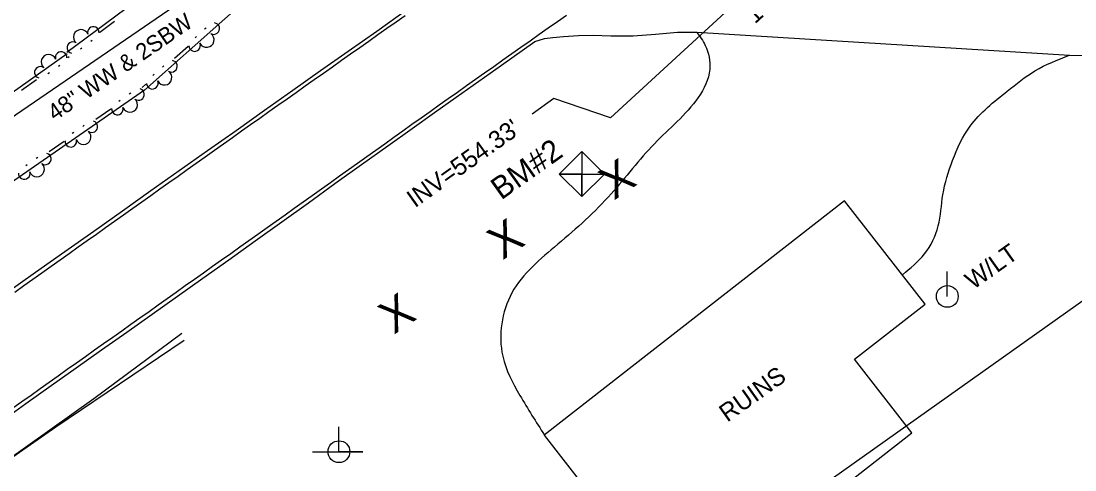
# Model space of a CAD drawing. Extents: x 1577032 to 1581865, y 611492 to 615011.
# Drawn here: x 1580168.3 to 1580404.9, y 613575.1 to 613675.8 of the extents above; entities that cross this region are included whole.
import ezdxf

# ---------------------------------------------------------------- set-up
doc = ezdxf.new("R2010")
doc.units = 0
for name, color, linetype in [('CTL Supplemental Vertical CELL', 7, 'Continuous'), ('CTL Supplemental Vertical Text', 7, 'Continuous'), ('Exist Guardrail', 7, 'Continuous'), ('Exist Other Culture Fence Line', 7, 'Continuous'), ('Exist Other Culture Fence Line Text', 7, 'Continuous'), ('Exist Property Owner Text', 7, 'Continuous'), ('Exist Right of Way Line', 7, 'Continuous'), ('Exist Roads EOP', 7, 'Continuous'), ('Exist Roads EOT', 7, 'Continuous'), ('Exist Structure Minor Pipes CMP 18 Inch Invert', 7, 'Continuous'), ('Exist Structure Minor Pipes CMP 18 Inch Leader', 7, 'Continuous'), ('Exist Structure Minor Pipes RCP 18 Inch', 7, 'Continuous'), ('Exist Structure Minor Pipes RCP 18 Inch Text', 7, 'Continuous'), ('Exist Utilities Power Joint Use Telephone CELL', 7, 'Continuous'), ('Exist Utilities Power Pole CELL', 7, 'Continuous'), ('Exist Utilities Power Pole Text', 7, 'Continuous'), ('Exist Vegetation Tree CELL', 7, 'Continuous'), ('Old_Level_11', 7, 'Continuous'), ('Old_Level_7', 7, 'Continuous'), ('Scratch_Level_4', 7, 'Continuous'), ('Scratch_Level_6', 7, 'Continuous')]:
    doc.layers.add(name, color=color, linetype=linetype)

msp = doc.modelspace()

# ---------------------------------------------------------------- linework, layer by layer
at = {"layer": 'CTL Supplemental Vertical CELL'}
msp.add_line((1580294.24, 613641.52), (1580294.24, 613641.52), dxfattribs=at)
for points in [[(1580289.16, 613641.49), (1580294.24, 613646.58), (1580299.32, 613641.49), (1580294.24, 613636.41), (1580289.16, 613641.49), (1580294.24, 613646.58), (1580299.32, 613641.49), (1580294.24, 613636.41), (1580289.16, 613641.49)], [(1580294.24, 613646.58), (1580294.24, 613636.41), (1580294.24, 613641.49), (1580289.16, 613641.49), (1580299.32, 613641.49)]]:
    msp.add_lwpolyline(points, dxfattribs=at)
at = {"layer": 'Exist Guardrail'}
msp.add_lwpolyline([(1580204.94, 613604.14), (1580176.13, 613584.66), (1580156.54, 613571.08), (1580137.28, 613557.36), (1580118.21, 613543.22), (1580106.98, 613535), (1580070.56, 613509.77), (1580039.34, 613487.9), (1579996.35, 613458.56), (1579960.14, 613434.1), (1579928.53, 613412.65), (1579891.13, 613387.42), (1579884.09, 613382.52), (1579876.58, 613377.52), (1579866.53, 613371.18), (1579856.35, 613364.93), (1579850.36, 613361.17), (1579845.45, 613357.94), (1579839.56, 613353.95), (1579830.4, 613347.61), (1579818.74, 613338.59)], dxfattribs=at)
at = {"layer": 'Exist Other Culture Fence Line'}
msp.add_line((1580098.64, 613607.82), (1580251.9, 613712.92), dxfattribs=at)
at = {"layer": 'Exist Right of Way Line'}
msp.add_line((1578304.92, 612120.6), (1580458.22, 613649.74), dxfattribs=at)
at = {"layer": 'Exist Roads EOP'}
for points in [[(1580254.88, 613678.24), (1580248.18, 613673.5), (1580241.77, 613668.98), (1580235.59, 613664.65), (1580229.34, 613660.25), (1580223, 613655.74), (1580216.6, 613651.2), (1580210.22, 613646.69), (1580203.84, 613642.2), (1580197.47, 613637.7), (1580191.09, 613633.18), (1580184.67, 613628.63), (1580178.17, 613624.03), (1580171.59, 613619.36), (1580164.85, 613614.58)], [(1580163.65, 613585.82), (1580169.43, 613589.97), (1580175.11, 613594.02), (1580180.75, 613598.02), (1580186.41, 613602.03), (1580192.1, 613606.04), (1580197.78, 613610.05), (1580203.45, 613614.05), (1580209.18, 613618.09), (1580215.01, 613622.24), (1580220.93, 613626.48), (1580226.88, 613630.75), (1580232.85, 613635.05), (1580238.81, 613639.34), (1580244.77, 613643.61), (1580250.66, 613647.81), (1580256.15, 613651.71), (1580261.18, 613655.29), (1580266.06, 613658.75), (1580271.12, 613662.33), (1580276.21, 613665.91), (1580283.68, 613671.25), (1580285.85, 613671.89), (1580287.7, 613672.14), (1580290.16, 613672.35), (1580293.46, 613672.55), (1580296.78, 613672.62), (1580300.73, 613672.52), (1580305.8, 613672.47), (1580310.79, 613672.84), (1580315.69, 613673.29), (1580320.02, 613673.33), (1580403.71, 613668.15)]]:
    msp.add_lwpolyline(points, dxfattribs=at)
msp.add_spline([(1580403.71, 613668.15), (1580454.87, 613667.32), (1580520.57, 613666.25), (1580608.23, 613664.83), (1580666.57, 613662.17), (1580712.03, 613659.84), (1580756.49, 613652.31), (1580801.49, 613639.76), (1580839.51, 613619.48), (1580875.28, 613593.59), (1580905.28, 613565.99), (1580935.48, 613537.65)], degree=3, dxfattribs=at)
at = {"layer": 'Exist Roads EOT'}
for points in [[(1580166.5, 613589), (1580168.54, 613590.45), (1580170.58, 613591.89), (1580172.61, 613593.34), (1580174.65, 613594.78), (1580176.69, 613596.23), (1580178.73, 613597.67), (1580180.77, 613599.12), (1580182.81, 613600.56), (1580184.84, 613602.01), (1580186.88, 613603.45), (1580188.92, 613604.9), (1580190.96, 613606.34), (1580193, 613607.78), (1580195.03, 613609.23), (1580197.07, 613610.67), (1580199.11, 613612.12), (1580201.15, 613613.56), (1580203.19, 613615.01), (1580205.22, 613616.45), (1580207.26, 613617.9), (1580209.3, 613619.34), (1580211.34, 613620.78), (1580213.38, 613622.23), (1580215.42, 613623.67), (1580217.45, 613625.12), (1580219.49, 613626.56), (1580221.53, 613628.01), (1580223.56, 613629.46), (1580225.6, 613630.91), (1580227.63, 613632.36), (1580229.67, 613633.81), (1580231.7, 613635.25), (1580233.73, 613636.7), (1580235.77, 613638.15), (1580237.8, 613639.6), (1580239.84, 613641.05), (1580241.87, 613642.5), (1580243.91, 613643.95), (1580245.94, 613645.4), (1580247.98, 613646.85), (1580250.01, 613648.3), (1580252.05, 613649.74), (1580254.08, 613651.19), (1580256.11, 613652.64), (1580258.15, 613654.09), (1580260.18, 613655.54), (1580262.22, 613656.99), (1580264.25, 613658.44), (1580266.29, 613659.88), (1580268.33, 613661.32), (1580270.37, 613662.76), (1580272.41, 613664.2), (1580274.46, 613665.64), (1580276.5, 613667.08), (1580278.54, 613668.52), (1580280.58, 613669.96), (1580282.62, 613671.4), (1580284.66, 613672.84), (1580286.7, 613674.28), (1580288.74, 613675.72), (1580290.78, 613677.16)], [(1580254.57, 613677.02), (1580252.53, 613675.58), (1580250.49, 613674.14), (1580248.45, 613672.7), (1580246.41, 613671.26), (1580244.37, 613669.82), (1580242.33, 613668.38), (1580240.29, 613666.93), (1580238.25, 613665.49), (1580236.21, 613664.05), (1580234.17, 613662.61), (1580232.13, 613661.17), (1580230.09, 613659.73), (1580228.05, 613658.29), (1580226.01, 613656.85), (1580223.97, 613655.41), (1580221.93, 613653.96), (1580219.89, 613652.52), (1580217.85, 613651.08), (1580215.81, 613649.64), (1580213.77, 613648.19), (1580211.74, 613646.75), (1580209.7, 613645.3), (1580207.66, 613643.86), (1580205.62, 613642.41), (1580203.59, 613640.96), (1580201.55, 613639.52), (1580199.51, 613638.07), (1580197.48, 613636.63), (1580195.44, 613635.18), (1580193.4, 613633.73), (1580191.36, 613632.29), (1580189.33, 613630.84), (1580187.29, 613629.4), (1580185.25, 613627.95), (1580183.22, 613626.5), (1580181.18, 613625.06), (1580179.14, 613623.61), (1580177.1, 613622.17), (1580175.07, 613620.72), (1580173.03, 613619.27), (1580171, 613617.83), (1580168.96, 613616.38), (1580166.92, 613614.93)]]:
    msp.add_lwpolyline(points, dxfattribs=at)
at = {"layer": 'Exist Structure Minor Pipes CMP 18 Inch Leader'}
msp.add_lwpolyline([(1580300.64, 613654.06), (1580287.96, 613658.4), (1580283.07, 613654.93)], dxfattribs=at)
at = {"layer": 'Exist Structure Minor Pipes RCP 18 Inch'}
msp.add_line((1580353.63, 613702.78), (1580300.64, 613654.06), dxfattribs=at)
msp.add_line((1580353.63, 613702.78), (1580300.64, 613654.06), dxfattribs=at)
at = {"layer": 'Exist Utilities Power Joint Use Telephone CELL'}
msp.add_line((1580239.7, 613579.18), (1580239.7, 613579.18), dxfattribs=at)
msp.add_lwpolyline([(1580233.77, 613579.18), (1580245.1, 613579.14), (1580239.7, 613579.16), (1580239.7, 613584.8)], dxfattribs=at)
msp.add_circle((1580239.71, 613579.18), 2.45, dxfattribs=at)
at = {"layer": 'Exist Utilities Power Pole CELL'}
for q in [(1580376.29, 613619.65), (1580376.29, 613614.03)]:
    msp.add_line((1580376.29, 613614.03), q, dxfattribs=at)
msp.add_circle((1580376.29, 613614.03), 2.45, dxfattribs=at)
at = {"layer": 'Old_Level_11'}
for points in [[(1580178.64, 613668.86), (1580237.64, 613712.65), (1580275.25, 613740.08), (1580305.41, 613763.08), (1580331.9, 613792.25), (1580348.57, 613817.56), (1580366.72, 613849.16), (1580382.81, 613883.89)], [(1580387.98, 613867.68), (1580362.26, 613826.06), (1580342.4, 613791.75), (1580326.53, 613768.18), (1580306.87, 613751.68), (1580263.54, 613718.08), (1580232.15, 613692.42), (1580196.05, 613660.28)], [(1580186.05, 613673.33), (1580189.34, 613675.78)], [(1580209.87, 613674.23), (1580209.56, 613673.96)], [(1580183.99, 613671.29), (1580184.32, 613671.54)], [(1580207.72, 613672.32), (1580207.41, 613672.05)], [(1580196.05, 613660.28), (1580125.81, 613611.65), (1580119.42, 613626.55), (1580178.67, 613668.56)], [(1580181.68, 613669.58), (1580182.01, 613669.83)], [(1580205.85, 613670.1), (1580202.78, 613667.38)], [(1580176.72, 613665.67), (1580177.06, 613665.91)], [(1580178.83, 613667.67), (1580179.14, 613667.89)], [(1580200.37, 613665.77), (1580200.06, 613665.5)], [(1580174.38, 613664.01), (1580174.72, 613664.25)], [(1580198.22, 613663.87), (1580197.92, 613663.6)], [(1580168.46, 613660.31), (1580171.8, 613662.68)], [(1580196.35, 613661.65), (1580195.5, 613660.89)], [(1580192.98, 613659.66), (1580192.65, 613659.42)], [(1580190.63, 613658.02), (1580190.29, 613657.79)], [(1580188.5, 613656.05), (1580185.13, 613653.72)], [(1580182.53, 613652.42), (1580182.2, 613652.19)], [(1580180.17, 613650.79), (1580179.83, 613650.55)], [(1580178.05, 613648.82), (1580174.67, 613646.48)], [(1580172.08, 613645.19), (1580171.74, 613644.95)], [(1580169.72, 613643.55), (1580169.38, 613643.32)]]:
    msp.add_lwpolyline(points, dxfattribs=at)
for centre, radius, start, end in [((1580211.6, 613674.13), 1.3, 240.1091, 80.9057), ((1580181.78, 613672.21), 1.69, 22.5515, 230.624), ((1580184.57, 613673.26), 1.3, 357.3562, 198.1528), ((1580210, 613671.61), 1.69, 207.6379, 55.7104), ((1580179.96, 613669.84), 1.3, 55.0227, 255.8192), ((1580207.31, 613670.31), 1.3, 182.4426, 23.2392), ((1580174.54, 613666.63), 1.69, 21.2995, 229.372), ((1580177.35, 613667.62), 1.3, 356.1042, 196.9008), ((1580172.67, 613664.3), 1.3, 53.7707, 254.5672), ((1580202.1, 613665.67), 1.3, 240.1091, 80.9057), ((1580200.51, 613663.15), 1.69, 207.6379, 55.7104), ((1580197.82, 613661.86), 1.3, 182.4426, 23.2392), ((1580194.7, 613659.35), 1.3, 233.1324, 73.9289), ((1580189.98, 613656.08), 1.3, 175.4659, 16.2625), ((1580192.8, 613657.04), 1.69, 200.6612, 48.7337), ((1580184.24, 613652.11), 1.3, 233.1324, 73.9289), ((1580179.52, 613648.84), 1.3, 175.4659, 16.2625), ((1580182.35, 613649.8), 1.69, 200.6612, 48.7337), ((1580173.79, 613644.87), 1.3, 233.1324, 73.9289), ((1580169.07, 613641.61), 1.3, 175.4659, 16.2625), ((1580171.9, 613642.56), 1.69, 200.6612, 48.7337)]:
    msp.add_arc(centre, radius, start, end, dxfattribs=at)
at = {"layer": 'Old_Level_7'}
msp.add_lwpolyline([(1580204.41, 613605.7), (1580184.66, 613591.04), (1580164.93, 613576.99), (1580138.26, 613557.96), (1580109.19, 613537.33), (1580079.14, 613516.2), (1580044.46, 613491.82), (1580020.63, 613475.12), (1579980.8, 613448.19), (1579942.82, 613422.24), (1579900.08, 613391.73), (1579828.5, 613345.35)], dxfattribs=at)
at = {"layer": 'Scratch_Level_4'}
for points in [[(1580320.02, 613673.33), (1580321.95, 613670.32), (1580322.95, 613665), (1580320.37, 613658.68), (1580310.52, 613648.29), (1580300.82, 613637.02), (1580288.85, 613625.72), (1580278.53, 613614.81), (1580276.48, 613600.61), (1580280.34, 613591.83), (1580285.83, 613582.93)], [(1580366.2, 613618.89), (1580371.19, 613623.59), (1580374.24, 613629.83), (1580375.3, 613636.85), (1580377.49, 613644.55), (1580381.41, 613652.24), (1580389.75, 613660.1), (1580395.97, 613664.65), (1580403.71, 613668.15)]]:
    msp.add_spline(points, degree=3, dxfattribs=at)
at = {"layer": 'Scratch_Level_6'}
msp.add_lwpolyline([(1580371.33, 613612.31), (1580353.23, 613635.51), (1580285.76, 613582.88), (1580312.74, 613548.3), (1580326.97, 613559.4), (1580318.07, 613570.81), (1580321.4, 613573.4), (1580334.32, 613556.85), (1580368.35, 613583.4), (1580355.46, 613599.93)], close=True, dxfattribs=at)

# ---------------------------------------------------------------- texts
at = {"layer": 'CTL Supplemental Vertical Text'}
msp.add_text('BM#2', height=5, rotation=35.38, dxfattribs=at).set_placement((1580276.12, 613635.53))
at = {"layer": 'Exist Other Culture Fence Line Text'}
msp.add_text('48" WW & 2SBW', height=3.6909, rotation=34.4427, dxfattribs=at).set_placement((1580175.92, 613653.27))
at = {"layer": 'Exist Property Owner Text'}
msp.add_text('LARRY E. & FRED L. HAMMILL, JR.', height=5, rotation=35.38, dxfattribs=at).set_placement((1580394.9, 613544.38))
at = {"layer": 'Exist Structure Minor Pipes CMP 18 Inch Invert'}
msp.add_text("INV=554.33'", height=4, rotation=35.38, dxfattribs=at).set_placement((1580256.77, 613633.79))
at = {"layer": 'Exist Structure Minor Pipes RCP 18 Inch Text'}
msp.add_text('18" RCP', height=4, rotation=42.5963, dxfattribs=at).set_placement((1580333.1, 613675.03))
at = {"layer": 'Exist Utilities Power Pole Text'}
msp.add_text('W/LT', height=4, rotation=35.38, dxfattribs=at).set_placement((1580382.1, 613615.42))
at = {"layer": 'Exist Vegetation Tree CELL'}
for p in [(1580301.46, 613635.53), (1580276.41, 613622.08), (1580252.01, 613605.37)]:
    msp.add_text('X', height=7.38, rotation=34.1625, dxfattribs=at).set_placement(p)
at = {"layer": 'Scratch_Level_6'}
msp.add_text('RUINS', height=4, rotation=35.38, dxfattribs=at).set_placement((1580326.89, 613585.69))

doc.saveas('drawing.dxf')
